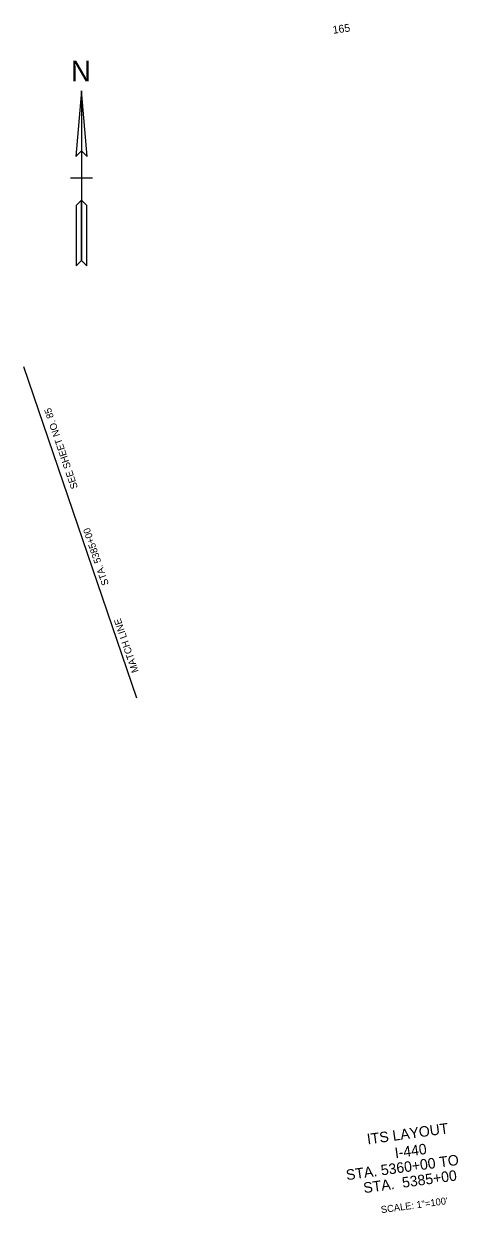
# Model space of a CAD drawing. Extents: x -200 to 1753069, y -325 to 654144.
# Drawn here: x 1752324 to 1753069, y 652105 to 654144 of the extents above; entities that cross this region are included whole.
import ezdxf

# ---------------------------------------------------------------- set-up
doc = ezdxf.new("R2010")
doc.units = 0
for name, color, linetype in [('DESIGN - CENTERLINE - Proposed Text', 7, 'Continuous'), ('DESIGN - SHEET - Corner Text', 7, 'Continuous'), ('ITS - CONST TEXT', 7, 'Continuous'), ('ITS - EXISTING COMM CABLE', 7, 'Continuous'), ('ITS - EXISTING HAR', 7, 'Continuous')]:
    doc.layers.add(name, color=color, linetype=linetype)

msp = doc.modelspace()

# ---------------------------------------------------------------- linework, layer by layer
at = {"layer": 'DESIGN - CENTERLINE - Proposed Text'}
for p, q in [((1752423.4, 653879.4), (1752404.5, 653879.4)), ((1752442.3, 653879.4), (1752423.4, 653879.4))]:
    msp.add_line(p, q, dxfattribs=at)
msp.add_lwpolyline([(1752423.4, 654029.4), (1752413.6, 653916.8), (1752423.4, 653926.6), (1752433.2, 653916.8), (1752423.4, 654029.4), (1752423.4, 653738.5), (1752432.5, 653729.4), (1752432.5, 653832.9), (1752423.4, 653842), (1752414.3, 653832.9), (1752414.3, 653729.4), (1752423.4, 653738.5)], dxfattribs=at)
for points in [[(1752423.4, 653926.6), (1752433.2, 653916.8), (1752423.4, 654029.4)], [(1752414.3, 653729.4), (1752423.4, 653738.5), (1752423.4, 653842), (1752414.3, 653832.9)]]:
    msp.add_lwpolyline(points, close=True, dxfattribs=at)
at = {"layer": 'ITS - EXISTING COMM CABLE'}
msp.add_line((1752518, 652987.9), (1752324.5, 653555.8), dxfattribs=at)

# ---------------------------------------------------------------- texts
at = {"layer": 'DESIGN - CENTERLINE - Proposed Text'}
msp.add_text('N', height=35.4, dxfattribs=at).set_placement((1752405.3, 654045.5))
at = {"layer": 'DESIGN - SHEET - Corner Text'}
msp.add_text('165', height=13.5, rotation=7.841, dxfattribs=at).set_placement((1752854.4, 654126.9))
at = {"layer": 'ITS - CONST TEXT'}
msp.add_text('SCALE: 1"=100\'', height=12, rotation=7.8411, dxfattribs=at).set_placement((1752937, 652105.1))
at = {"layer": 'ITS - EXISTING COMM CABLE'}
for s, p in [('SEE SHEET NO. 85 ', (1752417.3, 653349.1)), ('STA. 5385+00', (1752470.3, 653183.6)), ('MATCH LINE', (1752521.3, 653034))]:
    msp.add_text(s, height=12, rotation=108.8171, dxfattribs=at).set_placement(p)
at = {"layer": 'ITS - EXISTING HAR'}
for s, p in [('ITS LAYOUT', (1752913.6, 652223)), ('I-440', (1752961.2, 652199.4)), ('STA. 5360+00 TO', (1752877.7, 652161.6)), ('STA.  5385+00', (1752907.4, 652139.5))]:
    msp.add_text(s, height=18, rotation=7.8411, dxfattribs=at).set_placement(p)

doc.saveas('drawing.dxf')
